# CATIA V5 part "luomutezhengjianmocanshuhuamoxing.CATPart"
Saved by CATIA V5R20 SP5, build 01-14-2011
Part number: 螺母基础特征参数化建模
Bounding box of the stored display mesh (mm): x -30 to 30, y -25.981 to 25.981, z 0 to 15
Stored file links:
  E:\180522127 徐丽维\4.12\luomutezhengjianmocanshuhuamoxing.CATPart
  E:\180522127 徐丽维\4.12\DesignTable1.xls
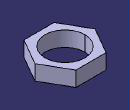
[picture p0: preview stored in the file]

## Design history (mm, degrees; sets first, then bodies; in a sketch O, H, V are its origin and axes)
Parameters
  `边长` = 30 mm {design table}
  `内孔半径` = 20 mm {design table}
  `柱高` = 15 mm {design table}
Body1 (main body)
  Sketch1 on xy-plane, origin (0, 0, 0), H (1, 0, 0), V (0, 1, 0)
    point P1 (-15, -25.9808)
    point P2 (15, -25.9808)
    point P3 (30, 0)
    point P4 (15, 25.9808)
    point P5 (-15, 25.9808)
    point P6 (-30, 0)
    point P7 (0, -25.9808)
    line L1 (-15, -25.9808) -> (15, -25.9808)
    line L2 (15, -25.9808) -> (30, 0)
    line L3 (30, 0) -> (15, 25.9808)
    line L4 (15, 25.9808) -> (-15, 25.9808)
    line L5 (-15, 25.9808) -> (-30, 0)
    line L6 (-30, 0) -> (-15, -25.9808)
    construction line L7 (0, 0) -> (0, -25.9808)
    construction circle A1 centre (0, 0) radius 30
    construction arc A2 centre (-15, 25.9808) radius 30 from (15, 25.9808) to (-30, 0) cw
    construction arc A3 centre (15, -25.9808) radius 30 from (30, 0) to (-15, -25.9808) ccw
    circle A4 centre (0, 0) radius 20
    radius A1 = 30 {= `边长`}
    radius A4 = 20 {= `内孔半径`}
    vertical: L7 V
    coincidence: A1 P1, A1 P2, A1 P3, A1 P4, A1 P5, A1 P6, A2 O, A3 O
    midpoint: P7 L1
    parallelism: L1 L4
  Pad1: profile Sketch1, direction (0, 0, 1), length 15 {= `柱高`}
Relations
  design table, configuration 1, drives `边长`, `内孔半径`, `柱高`
  rule:
    /*规则 创建者Student 2019-4-12*/
    if `内孔半径` < `边长` * sin(60deg )
    	Message("参数输入正确")
    else
    	Message("请重新输入参数: 边长，内孔直径，柱高")
  check:
    /*检查 创建者Student 2019-4-12*/
    `边长` > `内孔半径`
